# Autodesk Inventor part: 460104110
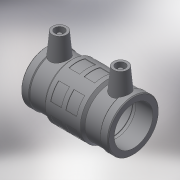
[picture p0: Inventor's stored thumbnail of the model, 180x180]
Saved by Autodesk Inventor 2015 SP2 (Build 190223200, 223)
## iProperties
Created: 2017-06
Part Number: 460104110
Material: Generic
Description: PLASSON LIGHTFIT COUPLER 110
Document SubType Name: Modeling
Designer: KIM
Mass: 89.5427 g
Surface Area: 304.58 cm^2
Volume: 89.5427 cm^3
Density: 1 g/cm^3
Appearance: Default
Author: KIM
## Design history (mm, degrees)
derived "460104.ipt"
feature "Solid1::460104.ipt"
tag "TaggingFeature1"
body "Solid1"
other parameters: "d13" = 163, "d14" = 17.6296, "d17" = 108.9, "d19" = 3.52592, "d20" = 168 deg, "d22" = 123.14, "d23" = 131, "d24" = 119.4458, "d25" = 135 deg, "d26" = 65.2, "d27" = 135 deg, "d29" = 79, "d35" = 15, "d39" = 5 deg, "d44" = 4, "d46" = 14, "d47" = 0, "d52" = 128.38, "d53" = 8.15, "d54" = 8.15, "d55" = 8.15, "d56" = 35 deg, "d58" = 360 deg, "d60" = 16, "d61" = 135 deg, "d62" = 68.46, "d63" = 3, "d64" = 0, "L_" = 163, "D_" = 131, "A_" = 79, "d_2" = 12
